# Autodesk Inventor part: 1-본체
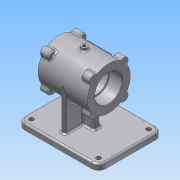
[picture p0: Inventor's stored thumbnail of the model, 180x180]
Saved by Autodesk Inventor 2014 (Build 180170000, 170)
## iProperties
Created: 2016-01
Part Number: 1-본체
Material: 알루미늄 6061
Document SubType Name: Modeling
Designer: Administrator
Density: 2.71 g/cm^3
Appearance: 알루미늄 - 평지
Mass: 1074.91 g
Surface Area: 834.653 cm^2
Volume: 396.647 cm^3
Author: Administrator
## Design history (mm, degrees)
sketch "스케치1"
  geometry: L1 (70, -55)-(-70, -55); L2 (-70, -55)-(-70, 55); L3 (-70, 55)-(70, 55); L4 (70, 55)-(70, -55); L5 (70, -55)-(-70, 55); L6 (-70, -55)-(70, 55); 1 further point
  constraints: 12 end point, 2 midpoint, 2 parallel, 1 horizontal, 1 perpendicular
  dimensions: "d0" = 140 distance of L2.end L3.end; "d1" = 110 distance of L3.end L1.start
extrude "돌출1" new body sketch "스케치1" distance "d2" = 10; taper "d3" = 0 deg
node "작업 평면6"
sketch "스케치7"
  geometry: L1 (0, 0)-(-110, 0) reference; C1 r 37 at (-55, 80); 2 further points
  constraints: 1 centre point, 1 midpoint, 1 vertical alignment
  dimensions: "d17" = 74 diameter of C1; "d18" = 80 distance from line of C1.centre L1
extrude "돌출4" join sketch "스케치7" stored distance "d19" = 85; taper "d20" = 0 deg
node "작업 평면7"
sketch "스케치8"
  geometry: L1 (-70, 55)-(-70, -55) reference; L2 (0, 37)-(-70, 37); L3 (0, -37)-(-70, -37); A1 r 37 centre (0, 0) between (0, 37) and (0, -37) reference; 1 further point
  constraints: 4 end point, 2 perpendicular, 2 point on circle, 2 point on line, 2 tangent
extrude "돌출5" join sketch "스케치8" stored distance "d21" = 8; taper "d22" = 0 deg
node "작업 평면8"
sketch "스케치9"
  geometry: L1 (-32.5, 43)-(52.5, 43) reference; L2 (-13, 10)-(0.341, 94.231); L3 (0.341, 94.231)-(23.659, 94.231); L4 (23.659, 94.231)-(37, 10); L5 (6, 80)-(14, 80) reference; L6 (14, 10)-(14, 80) reference; L7 (6, 10)-(14, 10) reference; L8 (6, 80)-(6, 10) reference; L9 (70, 10)-(-70, 10) reference; L10 (-13, 10)-(37, 10); 2 further points
  constraints: 8 end point, 2 point on line, 1 equal length, 1 horizontal
  dimensions: "d25" = 99 deg angle of L2 L9; "d26" = 50 distance of L4.end L2.start; "d27" = 6 distance from line of point (12, 10) L8; "d28" = 25 distance of point (12, 10) L2.start; "d30" = 25 distance of L4.end point (12, 10); "d31" = 84.23098 vertical distance of L4.end L3.end
extrude "돌출6" join sketch "스케치9" stored distance "d32" = 12; taper "d33" = 0 deg
sketch "스케치10"
  geometry: L1 (0, 0)-(37, 0); L2 (0, 0)-(26.163, 26.163); L3 (0, 0)-(-26.163, 26.163); L4 (0, 0)-(-26.163, -26.163); L5 (0, 0)-(26.163, -26.163); L6 (0, 0)-(-37, 0); A1 r 7 centre (26.163, 26.163) between (30.622, 20.767) and (20.767, 30.622); A2 r 7 centre (26.163, -26.163) between (20.767, -30.622) and (30.622, -20.767); A3 r 7 centre (-26.163, -26.163) between (-30.622, -20.767) and (-20.767, -30.622); A4 r 7 centre (-26.163, 26.163) between (-20.767, 30.622) and (-30.622, 20.767); 1 further point
  constraints: 12 end point, 8 point on circle, 4 centre point, 4 coincident, 3 equal radius, 1 collinear, 1 horizontal, 1 perpendicular, 15 other
  dimensions: "d34" = 45 deg angle of L1 L2; "d35" = 90 deg angle of L5 L2; "d36" = 45 deg angle of L6 L3; "d37" = 14 diameter of A2
extrude "돌출7" join sketch "스케치10" distance "d38" = 15; taper "d39" = 0 deg
sketch "스케치11"
  geometry: A1 r 7 centre (106.163, 28.837) between (100.767, 24.378) and (110.622, 34.233) reference; A2 r 7 centre (106.163, 81.163) between (110.622, 75.767) and (100.767, 85.622) reference; A3 r 7 centre (53.837, 81.163) between (59.233, 85.622) and (49.378, 75.767) reference; A4 r 7 centre (53.837, 28.837) between (49.378, 34.233) and (59.233, 24.378) reference; 5 further points
  constraints: 4 coincident
hole "구멍1" sketch "스케치11" at (106.163, 81.163), (106.163, 28.837), (53.837, 28.837), (53.837, 81.163) diameter "d40" = 3.242; stored, may be unused: countersink angle "d44" = 90 deg, drill point angle "d46" = 118 deg; dims "d41" = 9, "d42" = 4, "d43" = 2, "d45" = 11
hole "구멍2" diameter "d49" = 47; stored, may be unused: countersink angle "d53" = 90 deg, drill point angle "d55" = 0 deg; dims "d47" = 10, "d48" = 10, "d50" = 6, "d51" = 4, "d52" = 2, "d54" = 22
hole "구멍3" diameter "d58" = 42; stored, may be unused: countersink angle "d62" = 90 deg, drill point angle "d64" = 0 deg; dims "d56" = 10, "d57" = 10, "d59" = 6, "d60" = 4, "d61" = 2, "d63" = 41
node "작업 평면9"
node "작업 평면11"
sketch "스케치13"
  geometry: L1 (-52.5, 20.767)-(-52.5, -20.767) reference; C1 r 5 at (-10, 0); 2 further points
  constraints: 1 centre point, 1 horizontal alignment, 1 midpoint
  dimensions: "d66" = 42.5 distance from line of C1.centre L1; "d67" = 10 diameter of C1
extrude "돌출8" join sketch "스케치13" stored distance "d68" = 15; taper "d69" = 0 deg
sketch "스케치15"
  geometry: L1 (-70, -55)-(70, -55) reference; L2 (70, 55)-(-70, 55) reference; L3 (-70, 55)-(-70, -55) reference; L4 (-6, 37)-(-6, 6) reference; L5 (-58, 43)-(-58, -43); 3 further points
  constraints: 2 coincident, 2 end point, 1 parallel
  dimensions: "d72" = 12 distance from line of L5.start L3; "d73" = 12 distance from line of L5.start L2; "d74" = 12 distance from line of L5.end L1
hole "구멍4" sketch "스케치15" at (-58, 43), (-58, -43) diameter "d75" = 8; stored, may be unused: countersink angle "d79" = 90 deg, drill point angle "d81" = 0 deg; dims "d76" = 6, "d77" = 4, "d78" = 2, "d80" = 41
node "작업 평면12"
sketch "스케치16"
  geometry: L1 (55, -40)-(-55, -40); L2 (-55, -40)-(-55, 40); L3 (-55, 40)-(55, 40); L4 (55, 40)-(55, -40); L5 (55, -40)-(-55, 40); L6 (-55, -40)-(55, 40); C1 r 4 at (-58, 43) reference; C2 r 4 at (-58, -43) reference; C3 r 4 at (58, 43) reference; C4 r 4 at (58, -43) reference; A1 r 20 centre (-58, 43) between (-55, 23.226) and (-38.226, 40); A2 r 20 centre (-58, -43) between (-38.226, -40) and (-55, -23.226); A3 r 20 centre (58, -43) between (55, -23.226) and (38.226, -40); A4 r 20 centre (58, 43) between (38.226, 40) and (55, 23.226); 1 further point
  constraints: 12 end point, 8 point on circle, 8 point on line, 4 centre point, 4 coincident, 3 equal radius, 2 midpoint, 2 parallel, 1 horizontal, 1 perpendicular
  dimensions: "d82" = 110 distance of L2.end L3.end; "d83" = 80 distance of L1.end L2.end; "d84" = 40 diameter of A1
extrude "돌출9" cut sketch "스케치16" distance "d85" = 5; taper "d86" = 0 deg
node "작업 평면13"
sketch "스케치17"
  geometry: L1 (80, 55)-(80, 78.5); L2 (80, 55)-(135.083, 110.083); 1 further point
  constraints: 4 end point, 1 vertical, 1 vertical alignment, 1 other
  dimensions: "d87" = 45 deg angle of L2 L1
node "작업 평면14"
sketch "스케치19"
  geometry: 3 further points
  constraints: 1 coincident, 1 other
feature "엠보싱1" sketch "스케치19" dims "d88" = 0.5, "d89" = 0
hole "구멍5" diameter "d92" = 5.188; stored, may be unused: countersink angle "d96" = 90 deg, drill point angle "d98" = 0 deg; dims "d93" = 6, "d94" = 4, "d95" = 2, "d97" = 41, "d109" = 10, "d110" = 10
chamfer "모따기1" distance "d99" = 1; stored, may be unused: second distance "d100" = 2, angle "d101" = 45 deg
fillet "모깎기1" dims "d102" = 0.3
fillet "모깎기2" dims "d103" = 3
fillet "모깎기3" dims "d104" = 3
fillet "모깎기4" dims "d105" = 3
fillet "모깎기5" dims "d106" = 3
fillet "모깎기6" dims "d107" = 12
fillet "모깎기7" dims "d108" = 3
fillet "모깎기8" dims "d111" = 3
fillet "모깎기9" dims "d112" = 3
fillet "모깎기10" dims "d113" = 1
node "솔리드1"
mirror "대칭1"
mirror "대칭2"
node "투영된 루프1"
node "투영된 루프2"
other parameters: "d23" = 0, "d65" = 122
